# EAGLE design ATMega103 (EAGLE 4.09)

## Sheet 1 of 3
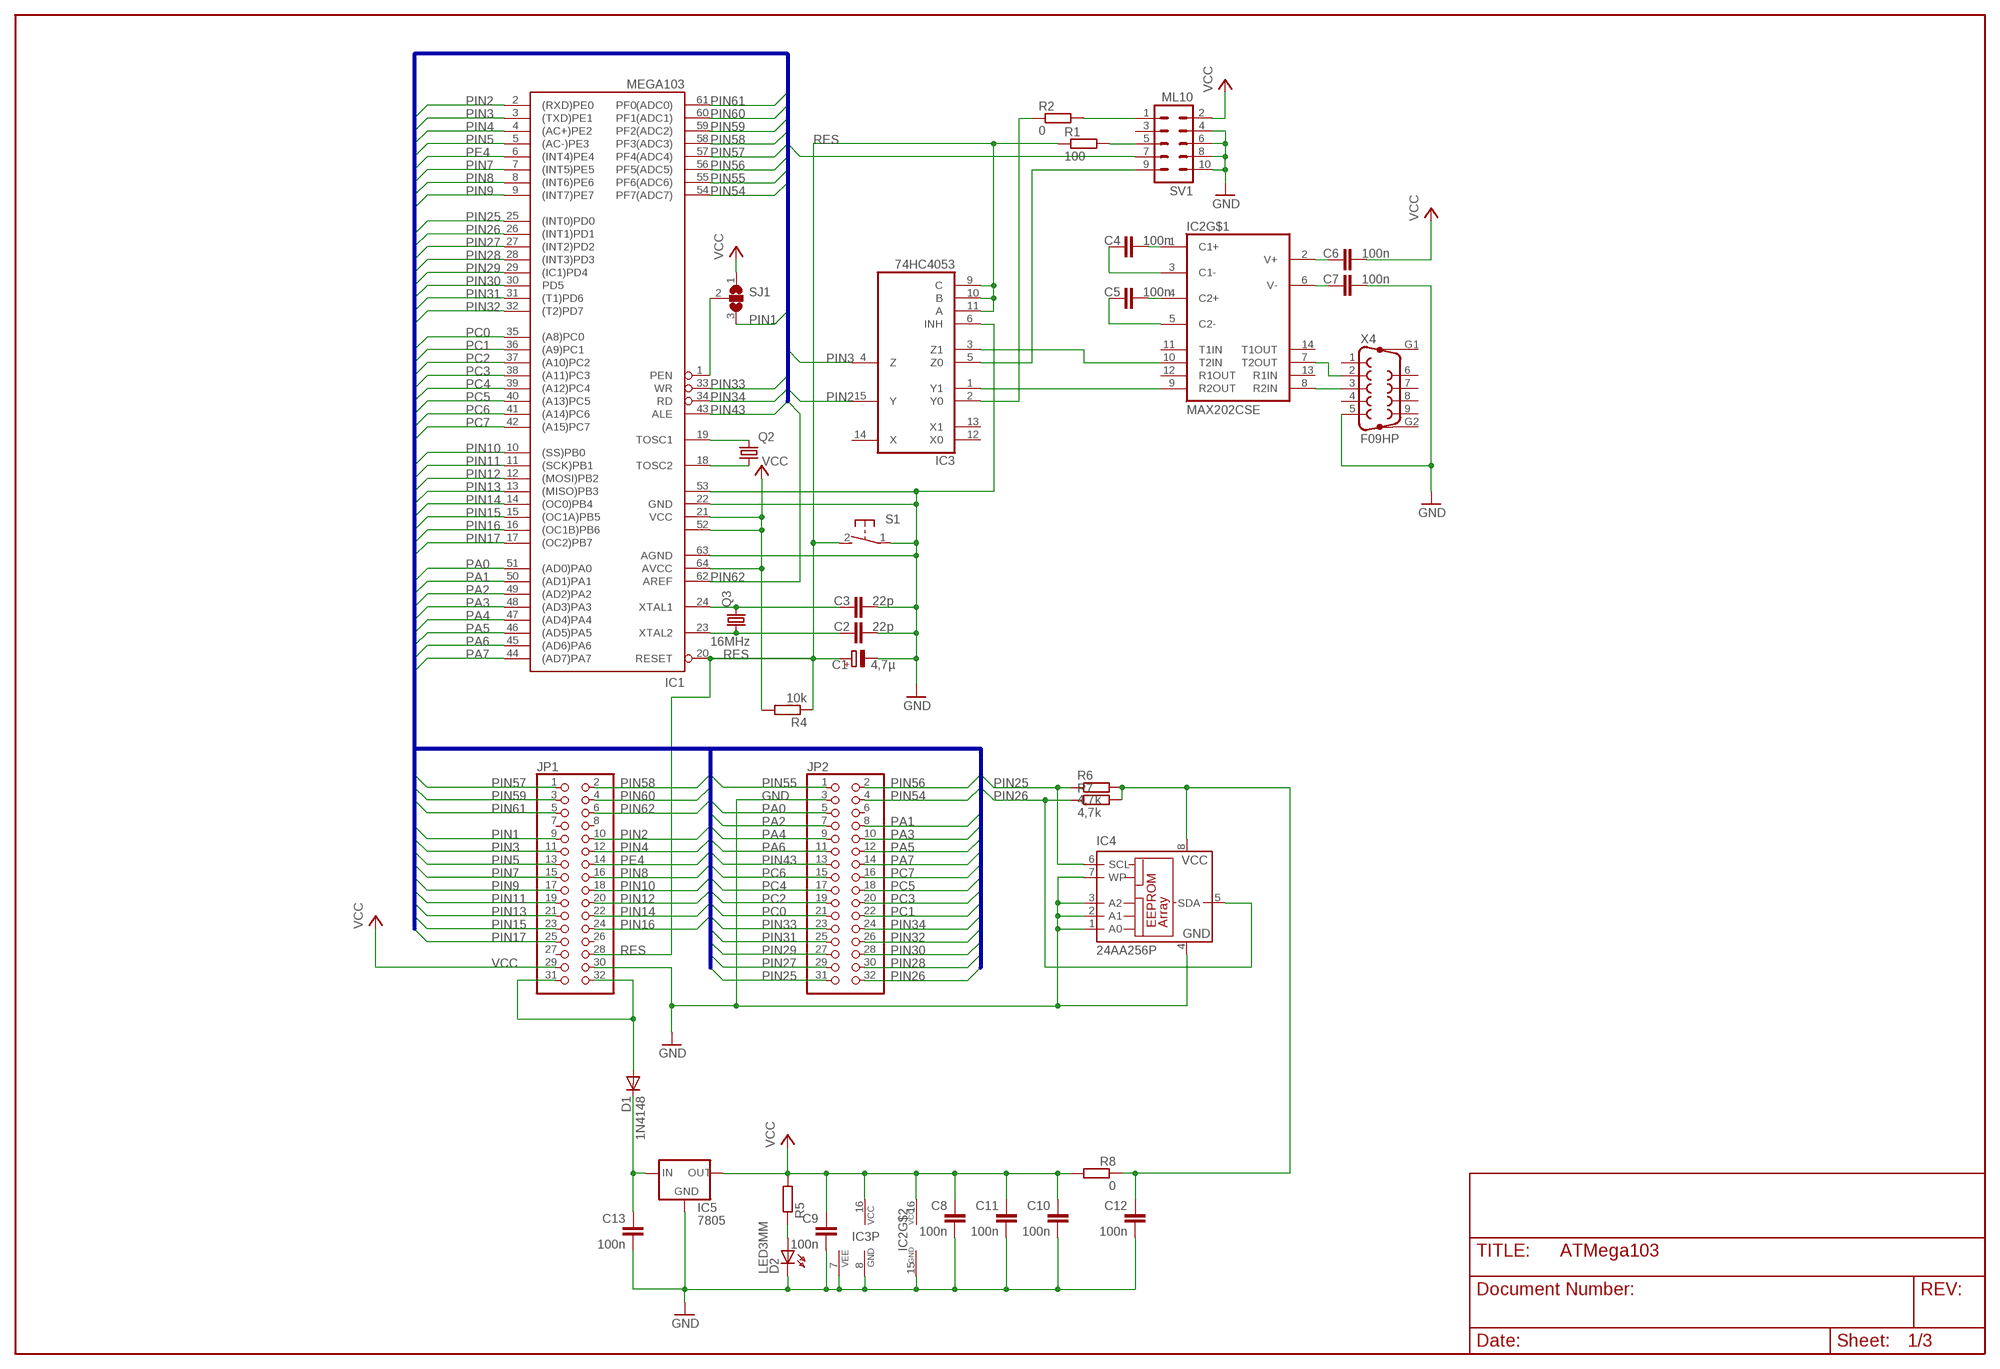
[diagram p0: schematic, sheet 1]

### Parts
C1  4,7µ  CPOL-EUE2-5  [E2-5]
C2  22p  C-EUC3216  [C3216]
C3  22p  C-EUC3216  [C3216]
C4  100n  C-EUC3216  [C3216]
C5  100n  C-EUC3216  [C3216]
C6  100n  C-EUC3216  [C3216]
C7  100n  C-EUC3216  [C3216]
C8  100n  C-EUC3216  [C3216]
C9  100n  C-EUC3216  [C3216]
C10  100n  C-EUC3216  [C3216]
C11  100n  C-EUC3216  [C3216]
C12  100n  C-EUC1206  [C1206]
C13  100n  C-EUC1206  [C1206]
D1  1N4148  DIODE-SOD106-R  [SOD106-R]
D2  LED3MM  [LED3MM]
IC1  MEGA103  [TQFP64]
IC2  MAX202CSE  [SO16]
IC3  74HC4053  4053D  [SO16]
IC4  24AA256P  [DIL8]
IC5  7805  78XXL  [78XXL]
JP1  PINHD-2X16  [2X16]
JP2  PINHD-2X16  [2X16]
Q2  TC26H  [TC26H]
Q3  16MHz  HC49/S  [HC49/S]
R1  100  R-EU_R3216  [R3216]
R2  0  R-EU_R3216  [R3216]
R4  10k  R-EU_R3216  [R3216]
R5  R-EU_R3216  [R3216]
R6  4,7k  R-EU_M3216  [M3216]
R7  4,7k  R-EU_M3216  [M3216]
R8  0  R-EU_R3216  [R3216]
S1  31-XX  [B3F-31XX]
SJ1  SJ2W  [SJ_2]
SV1  ML10  [ML10]
X4  F09HP  [F09HP]

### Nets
GND: C1.- C2.2 C3.2 C7.2 C8.2 C9.2 C10.2 C11.2 C12.2 C13.2 D2.K(C) IC1.22(GND) IC1.53(GND1) IC1.63(AGND) IC2.15(GND) IC3.6(INH) IC3.7(VEE) IC3.8(GND) IC4.1(A0) IC4.2(A1) IC4.3(A2) IC4.4(GND) IC4.7(WP) IC5.GND JP1.30 JP2.3 S1.1(P) SV1.4 SV1.6 SV1.8 SV1.10 X4.5 ; also sheet 2
N$1: C3.1 IC1.24(XTAL1) Q3.2
N$2: C2.1 IC1.23(XTAL2) Q3.1
N$3: IC1.19(TOSC1) Q2.1
N$4: IC1.18(TOSC2) Q2.2
N$9: D2.A R5.1
N$10: R2.2 SV1.1
N$11: D1.A JP1.31 JP1.32
N$12: IC1.1(PEN) SJ1.2
N$13: C12.1 IC4.8(VCC) R6.2 R7.2 R8.1
N$14: IC2.9(R2OUT) IC3.1(Y1)
N$16: IC3.5(Z0) SV1.9
N$17: IC3.2(Y0) R2.1
N$18: IC2.10(T2IN) IC3.3(Z1)
N$19: C4.2 IC2.1(C1+)
N$20: C5.2 IC2.4(C2+)
N$21: C5.1 IC2.5(C2-)
N$22: C6.1 IC2.2(V+)
N$23: C7.1 IC2.6(V-)
N$24: IC2.7(T2OUT) X4.2
N$25: IC2.8(R2IN) X4.3
N$26: C13.1 D1.C IC5.IN
N$28: R1.2 SV1.5
N$29: C4.1 IC2.3(C1-)
PA0: IC1.51((AD0)PA0) JP2.5 ; also sheet 2
PA1: IC1.50((AD1)PA1) JP2.8 ; also sheet 2
PA2: IC1.49((AD2)PA2) JP2.7 ; also sheet 2
PA3: IC1.48((AD3)PA3) JP2.10 ; also sheet 2
PA4: IC1.47((AD4)PA4) JP2.9 ; also sheet 2
PA5: IC1.46((AD5)PA5) JP2.12 ; also sheet 2
PA6: IC1.45((AD6)PA6) JP2.11 ; also sheet 2
PA7: IC1.44((AD7)PA7) JP2.14 ; also sheet 2
PC0: IC1.35((A8)PC0) JP2.21 ; also sheet 2
PC1: IC1.36((A9)PC1) JP2.22 ; also sheet 2
PC2: IC1.37((A10)PC2) JP2.19 ; also sheet 2
PC3: IC1.38((A11)PC3) JP2.20 ; also sheet 2
PC4: IC1.39((A12)PC4) JP2.17 ; also sheet 2
PC5: IC1.40((A13)PC5) JP2.18 ; also sheet 2
PC6: IC1.41((A14)PC6) JP2.15 ; also sheet 2
PC7: IC1.42((A15)PC7) JP2.16 ; also sheet 2
PE4: IC1.6((INT4)PE4) JP1.14 ; also sheet 2
PIN1: JP1.9 SJ1.3
PIN2: IC1.2((RXD)PE0) IC3.15(Y) JP1.10
PIN3: IC1.3((TXD)PE1) IC3.4(Z) JP1.11
PIN4: IC1.4((AC+)PE2) JP1.12
PIN5: IC1.5((AC-)PE3) JP1.13
PIN7: IC1.7((INT5)PE5) JP1.15
PIN8: IC1.8((INT6)PE6) JP1.16
PIN9: IC1.9((INT7)PE7) JP1.17
PIN10: IC1.10((SS)PB0) JP1.18
PIN11: IC1.11((SCK)PB1) JP1.19 SV1.7
PIN12: IC1.12((MOSI)PB2) JP1.20
PIN13: IC1.13((MISO)PB3) JP1.21
PIN14: IC1.14((OC0)PB4) JP1.22
PIN15: IC1.15((OC1A)PB5) JP1.23
PIN16: IC1.16((OC1B)PB6) JP1.24
PIN17: IC1.17((OC2)PB7) JP1.25
PIN25: IC1.25((INT0)PD0) IC4.6(SCL) JP2.31 R6.1
PIN26: IC1.26((INT1)PD1) IC4.5(SDA) JP2.32 R7.1
PIN27: IC1.27((INT2)PD2) JP2.29
PIN28: IC1.28((INT3)PD3) JP2.30
PIN29: IC1.29((IC1)PD4) JP2.27
PIN30: IC1.30(PD5) JP2.28
PIN31: IC1.31((T1)PD6) JP2.25
PIN32: IC1.32((T2)PD7) JP2.26
PIN33: IC1.33(WR) JP2.23
PIN34: IC1.34(RD) JP2.24
PIN43: IC1.43(ALE) JP2.13
PIN54: IC1.54(PF7(ADC7)) JP2.4
PIN55: IC1.55(PF6(ADC6)) JP2.1
PIN56: IC1.56(PF5(ADC5)) JP2.2
PIN57: IC1.57(PF4(ADC4)) JP1.1
PIN58: IC1.58(PF3(ADC3)) JP1.2
PIN59: IC1.59(PF2(ADC2)) JP1.3
PIN60: IC1.60(PF1(ADC1)) JP1.4
PIN61: IC1.61(PF0(ADC0)) JP1.5
PIN62: IC1.62(AREF) JP1.6
RES: C1.+ IC1.20(RESET) IC3.9(C) IC3.10(B) IC3.11(A) JP1.28 R1.1 R4.1 S1.2(S)
VCC: C6.2 C8.1 C9.1 C10.1 C11.1 IC1.21(VCC) IC1.52(VCC1) IC1.64(AVCC) IC2.16(VCC) IC3.16(VCC) IC5.OUT JP1.29 R4.2 R5.2 R8.2 SJ1.1 SV1.2 ; also sheet 2
Unconnected: IC2.11(T1IN) IC2.12(R1OUT) IC2.13(R1IN) IC2.14(T1OUT) IC3.12(X0) IC3.13(X1) IC3.14(X) JP1.7 JP1.8 JP1.26 JP1.27 JP2.6 SV1.3 X4.1 X4.4 X4.6 X4.7 X4.8 X4.9 X4.G1 X4.G2

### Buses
PIN[1..64]

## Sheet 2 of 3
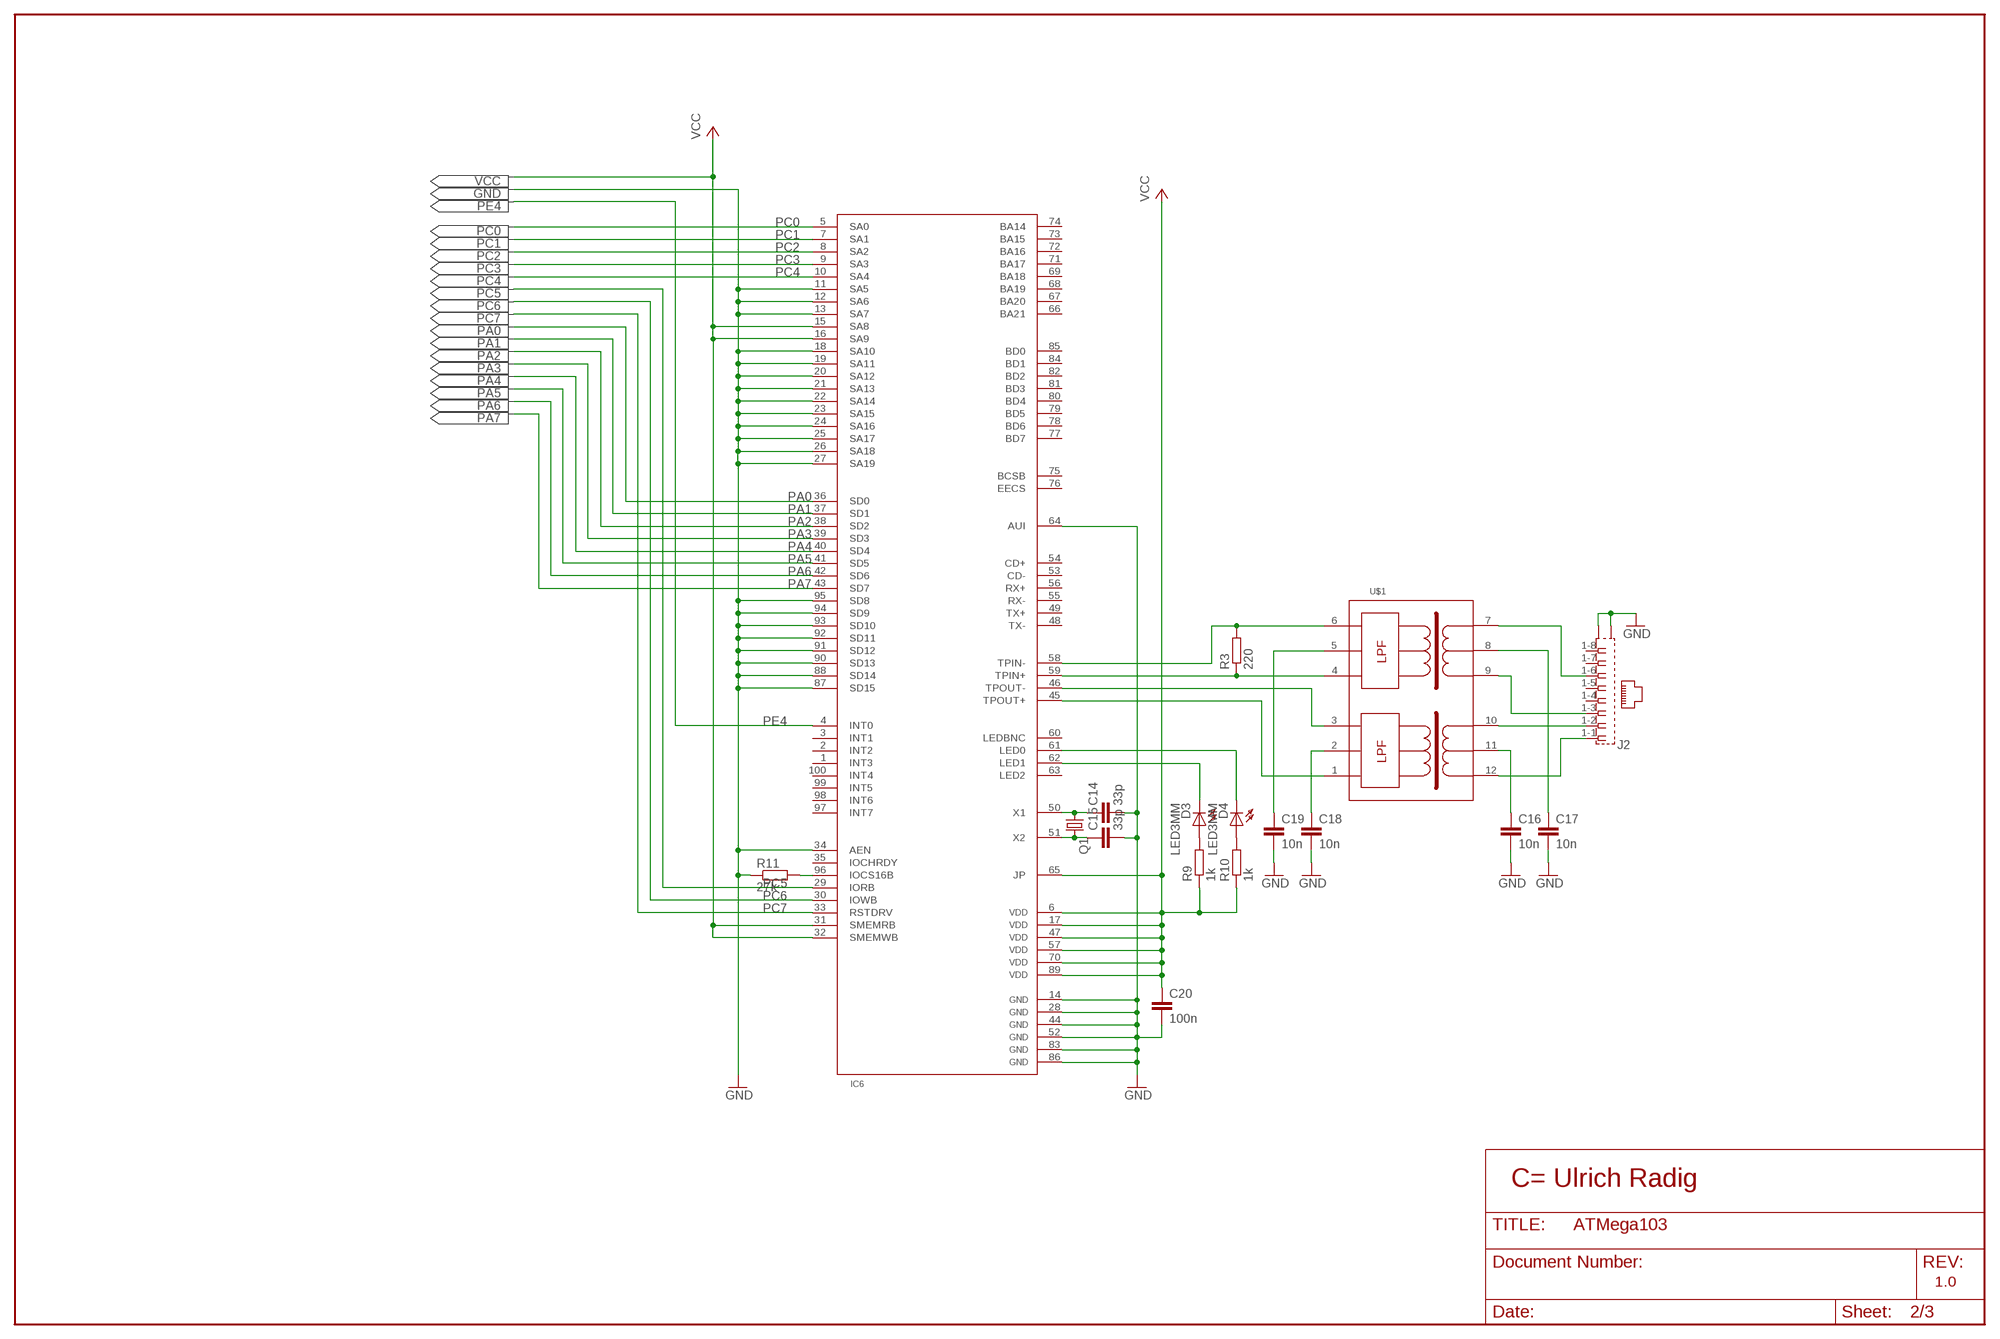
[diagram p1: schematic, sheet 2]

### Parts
C14  33p  C-EUC0805  [C0805]
C15  33p  C-EUC0805  [C0805]
C16  10n  C-EUC1206  [C1206]
C17  10n  C-EUC1206  [C1206]
C18  10n  C-EUC1206  [C1206]
C19  10n  C-EUC1206  [C1206]
C20  100n  C-EUC1206  [C1206]
D3  LED3MM  [LED3MM]
D4  LED3MM  [LED3MM]
IC6  RTL8019  [TQPF100]
J2  557786-1  [557786-1]
Q1  HC49U-H  [HC49U-H]
R3  220  R-EU_R1206  [R1206]
R9  1k  R-EU_M0805  [M0805]
R10  1k  R-EU_M0805  [M0805]
R11  27k  R-EU_M1206  [M1206]
U$1  20F001  [DIL16/12]

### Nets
GND: C14.2 C15.2 C16.2 C17.2 C18.2 C19.2 C20.2 IC6.11(SA5) IC6.12(SA6) IC6.13(SA7) IC6.14(G1) IC6.18(SA10) IC6.19(SA11) IC6.20(SA12) IC6.21(SA13) IC6.22(SA14) IC6.23(SA15) IC6.24(SA16) IC6.25(SA17) IC6.26(SA18) IC6.27(SA19) IC6.28(G2) IC6.34(AEN) IC6.44(G3) IC6.52(G4) IC6.64(AUI) IC6.83(G5) IC6.86(G6) IC6.87(SD15) IC6.88(SD14) IC6.90(SD13) IC6.91(SD12) IC6.92(SD11) IC6.93(SD10) IC6.94(SD9) IC6.95(SD8) J2.G1(S2) J2.G2(S1) R11.1 ; also sheet 1
N$15: J2.1-1 U$1.12
N$27: J2.1-2 U$1.10
N$30: J2.1-3 U$1.9
N$31: J2.1-6 U$1.7
N$32: IC6.58(TPIN-) R3.2 U$1.6
N$33: IC6.59(TPIN+) R3.1 U$1.4
N$34: IC6.46(TPOUT-) U$1.3
N$35: IC6.45(TPOUT+) U$1.1
N$36: C18.1 U$1.2
N$37: C19.1 U$1.5
N$38: C16.1 U$1.11
N$39: C17.1 U$1.8
N$40: C15.1 IC6.51(X2) Q1.2
N$41: C14.1 IC6.50(X1) Q1.1
N$42: D4.K(C) IC6.61(LED0)
N$43: D3.K(C) IC6.62(LED1)
N$44: D3.A R9.2
N$45: D4.A R10.2
N$46: IC6.96(IOCS16B) R11.2
PA0: IC6.36(SD0) ; also sheet 1
PA1: IC6.37(SD1) ; also sheet 1
PA2: IC6.38(SD2) ; also sheet 1
PA3: IC6.39(SD3) ; also sheet 1
PA4: IC6.40(SD4) ; also sheet 1
PA5: IC6.41(SD5) ; also sheet 1
PA6: IC6.42(SD6) ; also sheet 1
PA7: IC6.43(SD7) ; also sheet 1
PC0: IC6.5(SA0) ; also sheet 1
PC1: IC6.7(SA1) ; also sheet 1
PC2: IC6.8(SA2) ; also sheet 1
PC3: IC6.9(SA3) ; also sheet 1
PC4: IC6.10(SA4) ; also sheet 1
PC5: IC6.29(IORB) ; also sheet 1
PC6: IC6.30(IOWB) ; also sheet 1
PC7: IC6.33(RSTDRV) ; also sheet 1
PE4: IC6.4(INT0) ; also sheet 1
VCC: C20.1 IC6.6(V1) IC6.15(SA8) IC6.16(SA9) IC6.17(V2) IC6.31(SMEMRB) IC6.32(SMEMWB) IC6.47(V3) IC6.57(V4) IC6.65(JP) IC6.70(V5) IC6.89(V6) R9.1 R10.1 ; also sheet 1
Unconnected: IC6.1(INT3) IC6.2(INT2) IC6.3(INT1) IC6.35(IOCHRDY) IC6.48(TX-) IC6.49(TX+) IC6.53(CD-) IC6.54(CD+) IC6.55(RX-) IC6.56(RX+) IC6.60(LEDBNC) IC6.63(LED2) IC6.66(BA21) IC6.67(BA20) IC6.68(BA19) IC6.69(BA18) IC6.71(BA17) IC6.72(BA16) IC6.73(BA15) IC6.74(BA14) IC6.75(BCSB) IC6.76(EECS) IC6.77(BD7) IC6.78(BD6) IC6.79(BD5) IC6.80(BD4) IC6.81(BD3) IC6.82(BD2) IC6.84(BD1) IC6.85(BD0) IC6.97(INT7) IC6.98(INT6) IC6.99(INT5) IC6.100(INT4) J2.1-4 J2.1-5 J2.1-7 J2.1-8

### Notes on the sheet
- C= Ulrich Radig
- 1.0

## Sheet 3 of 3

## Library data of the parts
C1 = rcl:CPOL-EU: POLARIZED CAPACITOR, European symbol
C2-C20 = rcl:C-EU: CAPACITOR, European symbol
D1 = diode:DIODE-: DIODE
D2-D4 = led:LED3MM: LED
IC1 = atmel:MEGA103*: MICROCONTROLLER Low-voltage (L) 128 Kbytes FLASH 4 Kbytes SRAM 2 Kbytes EEPROM UART RTC 8-channel 10 bit ADC
IC2 = maxim:MAX202CSE
IC3 = 40xx:4053: Triple 2-channel ANALOG MULTIPLEXER
IC4 = microchip:24*: Serial EEPROM I2C
IC5 = v-reg:78XXL: VOLTAGE REGULATOR
IC6 = Realtek:RTL8019
J2 = con-amp:557786-1: AMP CONNECTOR
JP1 JP2 = pinhead:PINHD-2X16: PIN HEADER
Q1 = crystal:HC49U-H: CRYSTAL
Q2 = crystal:TC26H: CRYSTAL
Q3 = crystal:HC49/S: CRYSTAL
R1-R11 = rcl:R-EU_: RESISTOR, European symbol
S1 = switch-omron:31-XX: OMRON SWITCH
SJ1 = jumper:SJ2W: SMD solder JUMPER
SV1 = CON-ML:ML10
U$1 = Realtek:20F001
X4 = SUBD-A:F09HP

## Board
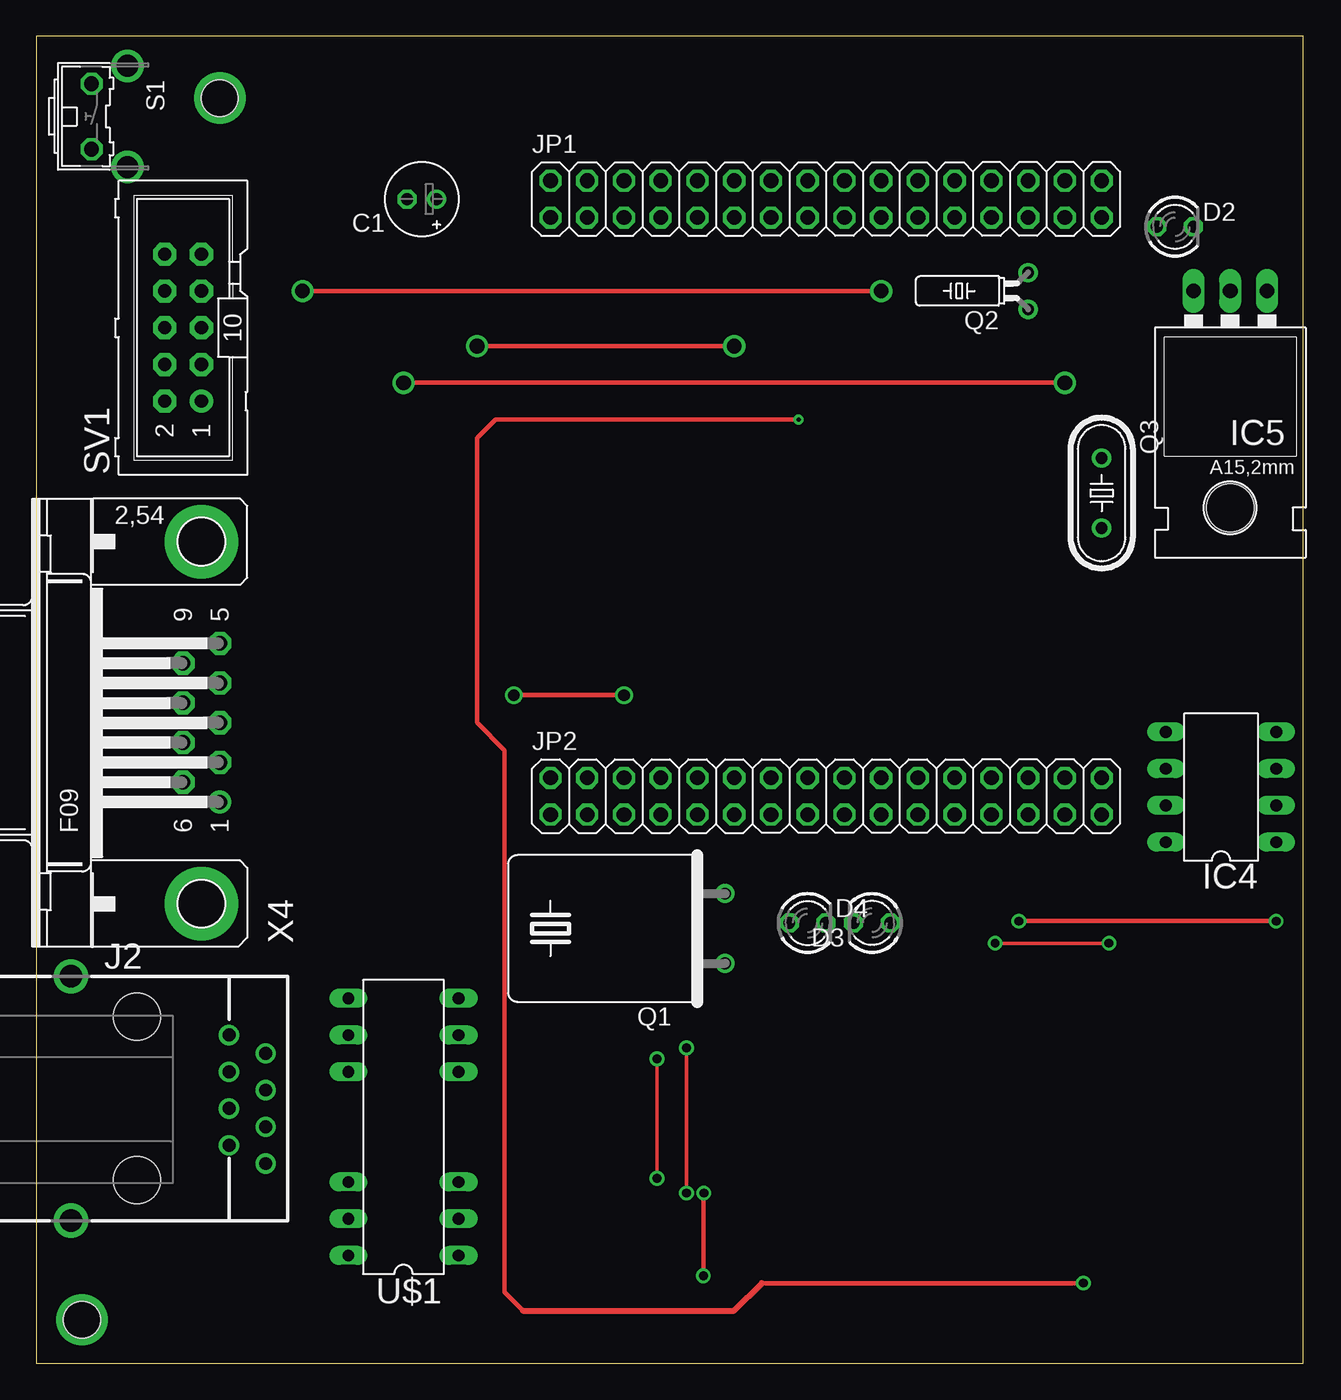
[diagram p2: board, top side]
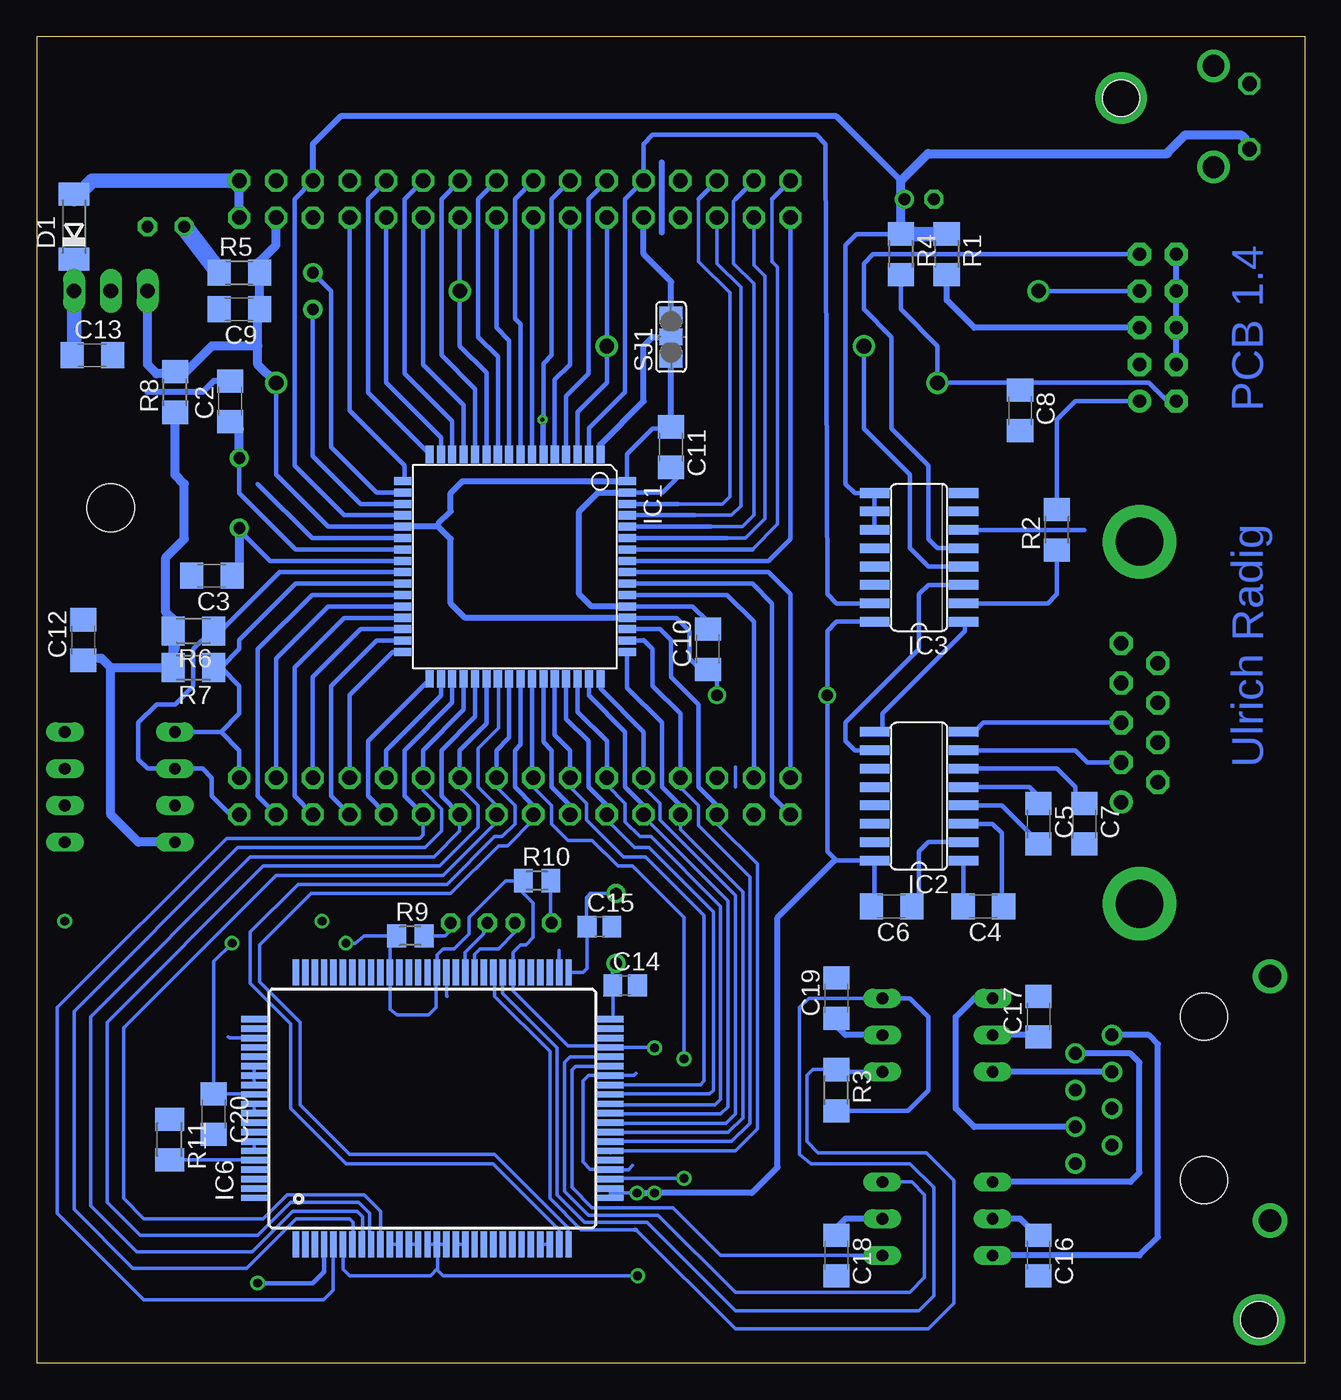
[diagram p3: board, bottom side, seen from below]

Size 87.61 x 91.74 mm. Coordinates in mm from the lower left corner, seen from the top.
Outline: 0,0 87.61,0 87.61,91.74 0,91.74 0,0
Copper layers (1*16): Top 0.035mm / dielectric 1.5mm / Bottom 0.035mm
Design rules "default": minimum track width 10mil, minimum drill 24mil, track to track 16mil, track to pad 16mil, pad to pad 16mil, via to via 16mil, smd to smd 16mil, copper to edge 40mil, drill to drill 8mil, minimum pad ring 10mil, minimum via ring 8mil, stop-mask expansion 4mil, vias tented up to drill 0mil, thermal gap 10mil
Holes 2.54 mm at 12.69,87.46 3.17,3.01

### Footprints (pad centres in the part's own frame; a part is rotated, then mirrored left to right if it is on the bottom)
E2-5 = drill 0.813 pad 1.27 round: + -1.016,0 | drill 0.813 pad 1.27 octagon: - 1.016,0
C3216 = smd 1.6 x 1.8: 1 -1.4,0; 2 1.4,0
C1206 = smd 1.6 x 1.8: 1 -1.4,0; 2 1.4,0
C0805 = smd 1.3 x 1.5: 1 -0.85,0; 2 0.85,0
SOD106-R = smd 1.6 x 2.1: A 2.25,0; C -2.25,0
LED3MM = drill 0.813 octagon: A -1.27,0; K 1.27,0
TQFP64 = smd 1.194 x 0.559: 1 -7.76,5.905; 2 -7.76,5.118; 3 -7.76,4.331; 4 -7.76,3.543; 5 -7.76,2.756; 6 -7.76,1.968; 7 -7.76,1.181; 8 -7.76,0.394; 9 -7.76,-0.394; 10 -7.76,-1.181; 11 -7.76,-1.968; 12 -7.76,-2.756; 13 -7.76,-3.543; 14 -7.76,-4.331; 15 -7.76,-5.118; 16 -7.76,-5.905; 33 7.76,-5.905; 34 7.76,-5.118; 35 7.76,-4.331; 36 7.76,-3.543; 37 7.76,-2.756; 38 7.76,-1.968; 39 7.76,-1.181; 40 7.76,-0.394; 41 7.76,0.394; 42 7.76,1.181; 43 7.76,1.968; 44 7.76,2.756; 45 7.76,3.543; 46 7.76,4.331; 47 7.76,5.118; 48 7.76,5.905 | smd 0.559 x 1.194: 17 -5.905,-7.76; 18 -5.118,-7.76; 19 -4.331,-7.76; 20 -3.543,-7.76; 21 -2.756,-7.76; 22 -1.968,-7.76; 23 -1.181,-7.76; 24 -0.394,-7.76; 25 0.394,-7.76; 26 1.181,-7.76; 27 1.968,-7.76; 28 2.756,-7.76; 29 3.543,-7.76; 30 4.331,-7.76; 31 5.118,-7.76; 32 5.905,-7.76; 49 5.905,7.76; 50 5.118,7.76; 51 4.331,7.76; 52 3.543,7.76; 53 2.756,7.76; 54 1.968,7.76; 55 1.181,7.76; 56 0.394,7.76; 57 -0.394,7.76; 58 -1.181,7.76; 59 -1.968,7.76; 60 -2.756,7.76; 61 -3.543,7.76; 62 -4.331,7.76; 63 -5.118,7.76; 64 -5.905,7.76
SO16 = smd 0.66 x 2.032: 1 -4.445,-3.073; 2 -3.175,-3.073; 3 -1.905,-3.073; 4 -0.635,-3.073; 5 0.635,-3.073; 6 1.905,-3.073; 7 3.175,-3.073; 8 4.445,-3.073; 9 4.445,3.073; 10 3.175,3.073; 11 1.905,3.073; 12 0.635,3.073; 13 -0.635,3.073; 14 -1.905,3.073; 15 -3.175,3.073; 16 -4.445,3.073
DIL8 = drill 0.813 long: 1 -3.81,-3.81; 2 -1.27,-3.81; 3 1.27,-3.81; 4 3.81,-3.81; 5 3.81,3.81; 6 1.27,3.81; 7 -1.27,3.81; 8 -3.81,3.81
78XXL = drill 1.016 long: GND 0,-3.81; IN -2.54,-3.81; OUT 2.54,-3.81 | hole 3.302: 0,11.176
TQPF100 = smd 1.8 x 0.44: 1 -9.395,9.425; 2 -9.395,8.775; 3 -9.395,8.125; 4 -9.395,7.475; 5 -9.395,6.825; 6 -9.395,6.175; 7 -9.395,5.525; 8 -9.395,4.875; 9 -9.395,4.225; 10 -9.395,3.575; 11 -9.395,2.925; 12 -9.395,2.275; 13 -9.395,1.625; 14 -9.395,0.975; 15 -9.395,0.325; 16 -9.395,-0.325; 17 -9.395,-0.975; 18 -9.395,-1.625; 19 -9.395,-2.275; 20 -9.395,-2.925; 21 -9.395,-3.575; 22 -9.395,-4.225; 23 -9.395,-4.875; 24 -9.395,-5.525; 25 -9.395,-6.175; 26 -9.395,-6.825; 27 -9.395,-7.475; 28 -9.395,-8.125; 29 -9.395,-8.775; 30 -9.395,-9.425; 51 9.395,-9.425; 52 9.395,-8.775; 53 9.395,-8.125; 54 9.395,-7.475; 55 9.395,-6.825; 56 9.395,-6.175; 57 9.395,-5.525; 58 9.395,-4.875; 59 9.395,-4.225; 60 9.395,-3.575; 61 9.395,-2.925; 62 9.395,-2.275; 63 9.395,-1.625; 64 9.395,-0.975; 65 9.395,-0.325; 66 9.395,0.325; 67 9.395,0.975; 68 9.395,1.625; 69 9.395,2.275; 70 9.395,2.925; 71 9.395,3.575; 72 9.395,4.225; 73 9.395,4.875; 74 9.395,5.525; 75 9.395,6.175; 76 9.395,6.825; 77 9.395,7.475; 78 9.395,8.125; 79 9.395,8.775; 80 9.395,9.425 | smd 0.44 x 1.8: 31 -6.175,-12.32; 32 -5.525,-12.32; 33 -4.875,-12.32; 34 -4.225,-12.32; 35 -3.575,-12.32; 36 -2.925,-12.32; 37 -2.275,-12.32; 38 -1.625,-12.32; 39 -0.975,-12.32; 40 -0.325,-12.32; 41 0.325,-12.32; 42 0.975,-12.32; 43 1.625,-12.32; 44 2.275,-12.32; 45 2.925,-12.32; 46 3.575,-12.32; 47 4.225,-12.32; 48 4.875,-12.32; 49 5.525,-12.32; 50 6.175,-12.32; 81 6.175,12.32; 82 5.525,12.32; 83 4.875,12.32; 84 4.225,12.32; 85 3.575,12.32; 86 2.925,12.32; 87 2.275,12.32; 88 1.625,12.32; 89 0.975,12.32; 90 0.325,12.32; 91 -0.325,12.32; 92 -0.975,12.32; 93 -1.625,12.32; 94 -2.275,12.32; 95 -2.925,12.32; 96 -3.575,12.32; 97 -4.225,12.32; 98 -4.875,12.32; 99 -5.525,12.32; 100 -6.175,12.32
557786-1 = drill 0.889 round: 1-1 -4.445,6.35; 1-2 -3.175,8.89; 1-3 -1.905,6.35; 1-4 -0.635,8.89; 1-5 0.635,6.35; 1-6 1.905,8.89; 1-7 3.175,6.35; 1-8 4.445,8.89 | drill 1.575 pad 2.184 round: G1 -8.509,-4.572; G2 8.382,-4.572 | hole 3.251: -5.715,0; 5.588,0
2X16 = drill 1.016 octagon: 1 -19.05,-1.27; 2 -19.05,1.27; 3 -16.51,-1.27; 4 -16.51,1.27; 5 -13.97,-1.27; 6 -13.97,1.27; 7 -11.43,-1.27; 8 -11.43,1.27; 9 -8.89,-1.27; 10 -8.89,1.27; 11 -6.35,-1.27; 12 -6.35,1.27; 13 -3.81,-1.27; 14 -3.81,1.27; 15 -1.27,-1.27; 16 -1.27,1.27; 17 1.27,-1.27; 18 1.27,1.27; 19 3.81,-1.27; 20 3.81,1.27; 21 6.35,-1.27; 22 6.35,1.27; 23 8.89,-1.27; 24 8.89,1.27; 25 11.43,-1.27; 26 11.43,1.27; 27 13.97,-1.27; 28 13.97,1.27; 29 16.51,-1.27; 30 16.51,1.27; 31 19.05,-1.27; 32 19.05,1.27
HC49U-H = drill 0.813 round: 1 -2.413,-5.08; 2 2.413,-5.08
TC26H = drill 0.813 round: 1 -1.27,0; 2 1.27,0
HC49/S = drill 0.813 round: 1 -2.413,0; 2 2.413,0
R3216 = smd 1.6 x 1.8: 1 -1.4,0; 2 1.4,0
R1206 = smd 1.6 x 1.803: 1 -1.422,0; 2 1.422,0
M3216 = smd 1.6 x 2: 1 -1.4,0; 2 1.4,0
M0805 = smd 1.3 x 1.6: 1 -0.95,0; 2 0.95,0
M1206 = smd 1.6 x 2: 1 -1.4,0; 2 1.4,0
B3F-31XX = drill 1.016 octagon: 1 -2.261,-1.245; 2 2.261,-1.245 | drill 1.499 pad 2.159 round: 3 -3.505,1.245; 4 3.505,1.245
SJ_2 = smd 1.168 x 1.6: 1 -1.524,0; 2 0,0; 3 1.524,0
ML10 = drill 0.914 pad 1.6 round: 1 -5.08,-1.27 | drill 0.914 pad 1.6 octagon: 2 -5.08,1.27; 3 -2.54,-1.27; 4 -2.54,1.27; 5 0,-1.27; 6 0,1.27; 7 2.54,-1.27; 8 2.54,1.27; 9 5.08,-1.27; 10 5.08,1.27
DIL16/12 = drill 0.813 long: 1 -8.89,-3.81; 2 -6.35,-3.81; 3 -3.81,-3.81; 4 3.81,-3.81; 5 6.35,-3.81; 6 8.89,-3.81; 7 8.89,3.81; 8 6.35,3.81; 9 3.81,3.81; 10 -3.81,3.81; 11 -6.35,3.81; 12 -8.89,3.81
F09HP = drill 1.016 pad 1.6 round: 1 -5.486,-1.27 | drill 1.016 pad 1.6 octagon: 2 -2.743,-1.27; 3 0,-1.27; 4 2.743,-1.27; 5 5.486,-1.27; 6 -4.115,1.27; 7 -1.372,1.27; 8 1.372,1.27; 9 4.115,1.27 | drill 3.302 pad 5.08 round: G1 -12.522,0; G2 12.522,0

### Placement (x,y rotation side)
C1  26.67,80.48 180 top
C2  74.29,66.51 90 bottom
C3  75.56,54.45 180 bottom
C4  22.22,31.59 180 bottom
C5  18.41,37.3 270 bottom
C6  28.57,31.59 180 bottom
C7  15.23,37.3 270 bottom
C8  19.68,65.88 270 bottom
C9  73.66,72.86 180 bottom
C10  41.27,49.37 90 bottom
C11  43.81,63.34 270 bottom
C12  84.45,50 90 bottom
C13  83.81,69.68 0 bottom
C14  46.98,26.12 0 bottom
C15  48.76,30.19 0 bottom
C16  18.41,7.46 270 bottom
C17  18.41,23.96 90 bottom
C18  32.38,7.46 270 bottom
C19  32.38,25.23 90 bottom
C20  75.43,17.23 270 bottom
D1  85.09,78.57 90 bottom
D2  78.73,78.57 0 top
D3  57.78,30.44 180 top
D4  53.34,30.44 0 top
IC1  54.6,55.08 270 bottom
IC2  26.67,39.2 90 bottom
IC3  26.67,55.72 90 bottom
IC4  81.91,39.84 90 top
IC5  82.55,70.32 180 top
IC6  60.32,17.62 90 bottom
J2  6.98,18.25 270 top
JP1  54.6,80.48 0 top
JP2  54.6,39.2 0 top
Q1  42.54,30.06 90 top
Q2  68.58,74.13 90 top
Q3  73.66,60.16 270 top
R1  24.76,76.67 270 bottom
R2  17.14,57.62 90 bottom
R3  32.38,18.89 270 bottom
R4  27.94,76.67 270 bottom
R5  73.66,75.4 0 bottom
R6  76.83,50.63 180 bottom
R7  76.83,48.09 180 bottom
R8  78.1,67.14 90 bottom
R9  61.84,29.55 0 bottom
R10  53.08,33.36 0 bottom
R11  78.48,15.46 270 bottom
S1  5.08,86.19 270 top
SJ1  43.81,70.95 90 bottom
SV1  10.15,71.59 90 top
U$1  25.39,16.35 90 top
X4  11.42,44.29 90 top

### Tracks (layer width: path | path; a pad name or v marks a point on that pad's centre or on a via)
GND  (via drill 0.61 pad 1.02)
  Top 0.305: v67.94,30.57 v85.72,30.57
  Bottom 0.254: IC6.27 52.83,8.22 52.82,8.22 IC6.28 | IC6.34 46.77,13.39 46.48,13.68 | IC6.19 58.16,8.22 IC6.18 | IC6.13 61.85,8.22 61.84,8.22 IC6.14 | 63.36,8.22 IC6.11 | IC6.12 63.36,8.22 | 63.36,8.22 63.37,8.22 | IC6.44 46.36,19.89 46.22,20.03 | 39.36,39.84 39.36,41.24 | IC6.52 51.56,27.02 51.56,28.54 | 48.76,19.9 49.52,19.9 49.91,19.52 49.91,13.93 49.4,13.42 48,13.42 | IC6.83 74.34,22.49 74.42,22.57 | IC6.86 72.64,19.9 IC6.87 72.64,19.27 IC6.88 | IC6.90 72.64,17.87 IC6.91 | IC6.94 72.64,15.33 IC6.95 | IC6.64 59.34,25.4 59.3,25.36
  Bottom 0.305: IC1.22 68.64,57.05 72.39,60.8 | IC1.63 44.41,60.2 43.17,61.43 | 15.23,57.62 IC3.6 | IC1.53 42.32,52.32 41.27,51.27 | IC6.44 48.12,19.89 48.13,19.9 48.76,19.9 | IC6.34 48,13.42
  Bottom 0.406: SV1.10 SV1.8 SV1.6 SV1.4 | IC1.63 48.85,60.2 50.16,58.89 50.16,53.18 49.31,52.32 IC1.53 | C2.2 75.43,67.91 76.2,67.14 80.01,67.14 | C10.2 41.27,51.27 | 44.45,78.19 44.45,83.02
N$1
  Bottom 0.305: IC1.24 71.51,55.47 73.66,57.62
  Bottom 0.406: 74.16,54.58 C3.1 | 73.66,57.62 Q3.2
  Bottom 0.61: 73.66,57.62 73.66,54.45 73.79,54.58 74.16,54.58
N$2
  Bottom 0.305: IC1.23 69.76,56.26 73.66,60.16 Q3.1 73.66,62.7 | C2.1 74.29,65.24 73.66,64.6
  Bottom 0.61: Q3.1 73.66,64.6
N$3
  Bottom 0.305: IC1.19 65.29,59.41 68.58,62.7 Q2.1
N$4
  Bottom 0.305: IC1.18 64.17,60.2 67.31,63.34 67.31,74.13 Q2.2
N$5  (via drill 2.54)
  other vias: 12.69,87.46
N$8  (via drill 2.54)
  other vias: 3.17,3.01
N$9
  Bottom 1.27: R5.1 D2.A
N$10
  Bottom 0.305: SV1.1 15.87,66.51 17.14,65.24 R2.2 17.14,58.89
N$11
  Bottom 0.61: JP1.31 JP1.32 | 85.09,80.48 D1.A
  Bottom 1.016: JP1.32 83.81,81.75 85.09,80.48
N$12
  Bottom 0.406: SJ1.2 45.08,70.95 45.71,70.32 45.71,66.51 48.7,63.53 IC1.1
N$13
  Bottom 0.406: 84.45,48.73 C12.1
  Bottom 0.61: R8.1 78.1,61.43 77.47,60.8 77.47,56.98 78.73,55.72 78.73,51.91 78.1,51.27 78.1,49.37 R6.2 78.23,48.23 | 78.1,48.09 R7.2 78.23,48.23 | 78.1,48.09 78.23,48.23 | IC4.8 80.64,36.03 82.55,37.94 82.55,48.09 | 82.55,48.09 78.1,48.09 | 84.45,48.73 83.18,48.73 82.55,48.09
N$14
  Bottom 0.305: IC3.1 23.49,51.27 23.49,50.63 29.21,44.92 29.21,43.65 IC2.9 29.84,43.65
N$15
  Bottom 0.406: J2.1-1 10.79,22.7 10.15,22.06 10.15,8.73 11.42,7.46 U$1.12
N$16
  Bottom 0.305: SV1.9 29.84,76.67 30.48,76.03 30.48,72.86 28.57,70.95 28.57,64.6 26.03,62.06 26.03,56.98 25.39,56.35 IC3.5 23.49,56.35
N$17
  Bottom 0.305: IC3.2 17.78,52.54 17.14,53.18 R2.1
N$18
  Bottom 0.305: IC3.3 26.03,53.81 26.67,53.18 26.67,49.37 31.75,44.29 31.75,43.02 31.11,42.38 IC2.10
N$19
  Bottom 0.305: C4.2 23.49,31.59 23.59,31.69 IC2.1
N$20
  Bottom 0.305: IC2.4 20.95,38.57 18.41,36.03 C5.2
N$21
  Bottom 0.305: C5.1 18.41,39.2 19.05,39.84 IC2.5
N$22
  Bottom 0.305: IC2.2 26.03,36.03 26.67,35.4 26.67,32.22 27.3,31.59 C6.1
N$23
  Bottom 0.305: C7.1 15.87,38.7 | 15.87,38.7 15.87,38.57 | 15.87,38.7 15.87,39.84 17.14,41.11 IC2.6
N$24
  Bottom 0.305: X4.2 15.03,41.54 15.87,42.38 IC2.7
N$25
  Bottom 0.305: IC2.8 22.86,43.65 22.22,44.29 X4.3
N$26
  Bottom 0.61: C13.1 85.09,69.68
  Bottom 1.016: 85.09,69.68 IC5.IN D1.C
N$27
  Bottom 0.406: J2.1-2 12.06,21.43 11.42,20.79 11.42,13.17 12.06,12.54 U$1.10
N$28
  Bottom 0.406: SV1.5 22.86,71.59 24.76,73.49 R1.2
N$29
  Bottom 0.305: IC2.3 21.59,37.3 20.95,36.66 20.95,31.59 C4.1
N$30
  Bottom 0.406: J2.1-3 U$1.9
N$31
  Bottom 0.406: J2.1-6 22.86,16.35 24.12,17.62 24.12,23.96 22.86,25.23 U$1.7
N$32
  Bottom 0.254: IC6.58 55.45,25.57 51.68,21.81 51.68,11.65 49.78,9.74 45.46,9.74 39.36,3.65 26.67,3.65 25.65,4.66 25.65,12.15 27.3,13.81 34.16,13.81 34.92,14.44 34.92,24.6 34.28,25.23 29.46,25.23 29.33,25.36 U$1.6
  Bottom 0.305: R3.2 27.45,17.46 26.03,18.89 26.03,23.96 27.3,25.23 U$1.6
N$33
  Bottom 0.254: R3.1 34.01,20.31 34.41,19.9 34.41,15.33 33.65,14.57 26.16,14.57 24.25,12.66 24.25,4.15 26.03,2.38 39.36,2.38 46.22,9.23 | 46.35,9.23 50.03,9.23 52.19,11.39 52.19,21.55 56,25.36 56,26.89 56.13,27.01 | 56.13,27.01 | 56.13,27.01 IC6.59
  Bottom 0.305: R3.1 32.38,20.16 U$1.4 | 46.22,9.23 46.35,9.23
N$34
  Bottom 0.254: U$1.3 27.17,12.54 26.28,11.65 26.28,5.93 27.3,4.92 39.36,4.92 44.7,10.25 49.52,10.25 51.18,11.9 51.18,20.79 50.79,21.17 48.13,21.17 48,21.3 IC6.46
N$35
  Bottom 0.254: U$1.1 40.38,7.46 43.68,10.76 49.27,10.76 50.67,12.15 50.67,20.28 50.41,20.54 IC6.45
N$36
  Bottom 0.406: U$1.2 31.75,10 32.38,9.36 C18.1 32.38,8.73
N$37
  Bottom 0.406: C19.1 32.38,23.33 31.75,22.7 U$1.5
N$38
  Bottom 0.406: C16.1 18.54,8.86 19.68,10 U$1.11
N$39
  Bottom 0.406: C17.1 18.41,22.7 U$1.8
N$40
  Bottom 0.254: Q1.2 49.4,32.47 49.65,32.22 49.65,30.32 49.52,30.19 C15.1 49.61,27.31 49.91,27.01 50.79,27.01 IC6.51
N$41
  Bottom 0.254: Q1.1 47.87,27.78 47.87,26.38 47.75,26.25 47.84,26.16 C14.1 47.84,24 48,23.84 IC6.50
N$42
  Bottom 0.254: D4.K 54.6,29.81 55.75,28.66 57.02,28.66 57.4,28.28 IC6.61
N$43
  Bottom 0.254: IC6.62 58.03,28.41 56.76,29.68 56.76,30.19 D3.K
N$44
  Bottom 0.254: D3.A 59.05,29.93 59.43,29.55 R9.2
N$45
  Bottom 0.254: D4.A 52.06,30.57 52.13,30.64 R10.2
N$46
  Bottom 0.254: 72.77,14.06 72.77,14.04 IC6.96 | 72.77,14.06 R11.2 | 72.77,14.06
PA0
  Bottom 0.254: 48,14.57 | 48,14.57 IC6.36 | 48,14.57 47.87,14.69 39.36,14.69 37.84,16.22 37.84,34.51 40.63,37.3 JP2.5
  Bottom 0.305: JP2.5 40.63,38.57 41.9,39.84 41.9,45.55 43.81,47.46 43.81,50 44.56,50.75 IC1.51
PA1
  Bottom 0.254: 43.17,39.84 43.17,39.71 43.05,39.71 41.9,38.57 41.9,37.17 38.35,33.62 38.35,16.6 39.62,15.33 47.87,15.33 47.88,15.34 IC6.37
  Bottom 0.305: 45.68,49.96 IC1.50 | 45.68,49.96 45.71,50 | 45.68,49.96 45.08,49.37 45.08,46.83 43.17,44.92 JP2.8 43.17,39.84
PA2
  Bottom 0.254: JP2.7 43.17,36.92 38.86,32.6 38.86,16.98 39.87,15.96 48,15.96 IC6.38
  Bottom 0.305: JP2.7 43.17,38.57 44.45,39.84 44.45,44.29 46.84,46.69 IC1.49
PA3
  Bottom 0.254: JP2.10 45.71,39.84 44.57,38.7 44.57,37.55 39.36,32.35 39.36,17.23 40,16.6 48,16.6 IC6.39
  Bottom 0.305: IC1.48 48.7,46.63 45.71,43.65 JP2.10
PA4
  Bottom 0.254: JP2.9 45.71,37.81 39.87,31.97 39.87,17.74 40.38,17.23 47.87,17.23 48,17.36 | 48,17.36 | 48,17.36 IC6.40
  Bottom 0.305: IC1.47 49.49,46.15 46.98,43.65 46.98,39.84 45.71,38.57 JP2.9
PA5
  Bottom 0.254: JP2.12 48.25,39.97 46.98,38.7 46.98,37.43 45.97,36.41 45.21,36.41 40.38,31.59 40.38,18.25 40.76,17.87 47.87,17.87 48,18 | 48,18 | 48,18 IC6.41
  Bottom 0.305: IC1.46 50.27,45.03 48.25,43.02 JP2.12
PA6
  Bottom 0.254: JP2.11 48.25,37.55 46.35,35.65 45.33,35.65 40.89,31.2 40.89,18.89 41.14,18.63 47.87,18.63 48,18.63 | 48,18.63 | 48,18.63 IC6.42
  Bottom 0.305: IC1.45 51.06,44.55 49.52,43.02 49.52,39.84 48.25,38.57 JP2.11
PA7
  Bottom 0.254: JP2.14 50.79,39.84 49.65,38.7 49.65,37.55 47.11,35.01 45.59,35.01 41.52,30.95 41.52,19.52 41.78,19.27 48,19.27 IC6.43
  Bottom 0.305: IC1.44 51.85,43.43 50.79,42.38 JP2.14
PC0
  Bottom 0.254: JP2.21 60.95,36.54 61.21,36.28 74.54,36.28 86.23,24.6 86.23,10.38 80.26,4.41 67.81,4.41 67.18,5.04 67.18,8.09 67.05,8.22 IC6.5
  Bottom 0.305: IC1.35 58.94,45.67 62.22,42.38 62.22,39.2 JP2.21
PC1
  Bottom 0.254: JP2.22 60.95,39.59 59.68,38.32 59.68,36.79 60.83,35.65 73.78,35.65 85.09,24.35 85.09,10.63 81.02,6.57 73.15,6.57 69.72,10 66.04,10 65.78,9.74 65.78,8.09 65.84,8.15 IC6.7
  Bottom 0.305: IC1.36 58.15,45.19 60.95,42.38 JP2.22
PC2
  Bottom 0.254: JP2.19 58.41,36.79 60.19,35.01 72.89,35.01 83.94,23.96 83.94,10.88 80.77,7.71 72.77,7.71 69.97,10.5 65.53,10.5 65.15,10.12 65.15,8.22 IC6.8
  Bottom 0.305: IC1.37 57.36,44.7 59.68,42.38 59.68,39.2 JP2.19
PC3
  Bottom 0.254: JP2.20 58.41,39.84 57.14,38.57 57.14,37.05 59.81,34.38 72,34.38 82.8,23.58 82.8,11.14 80.51,8.85 72.39,8.85 70.1,11.14 65.4,11.14 64.64,10.38 64.64,8.22 64.55,8.12 | 64.55,8.12 64.51,8.09 | IC6.9 64.55,8.12
  Bottom 0.305: IC1.38 56.57,44.22 58.41,42.38 JP2.20
PC4
  Bottom 0.254: IC6.10 63.88,8.22 63.88,10.5 65.02,11.65 70.35,11.65 72,10 80.26,10 81.66,11.39 81.66,23.2 71.12,33.74 59.56,33.74 55.88,37.43 JP2.17 55.88,38.57 57.14,39.84 57.14,42.51 55.75,43.9 55.75,47.21 55.79,47.24 IC1.39
PC5
  Bottom 0.254: JP2.18 55.88,39.84 54.6,38.57 54.6,37.3 55.49,36.41 56,36.41 59.3,33.11 69.59,33.11 72.89,29.81 72.89,26.25 70.1,23.46 70.1,17.62 66.29,13.81 56.13,13.81 51.56,9.23 51.56,8.22 IC6.29
  Bottom 0.305: IC1.40 55,43.26 55.88,42.38 JP2.18
PC6
  Bottom 0.254: JP2.15 53.34,37.55 55.11,35.78 55.75,35.78 59.05,32.47 68.7,32.47 72.26,28.92 72.26,26.38 69.46,23.58 69.46,17.87 66.04,14.44 56,14.44 50.92,9.36 50.92,8.22 IC6.30
  Bottom 0.305: IC1.41 54.21,42.77 54.6,42.38 54.6,39.84 53.34,38.57 JP2.15
PC7  (via drill 0.61)
  Top 0.254: v42.92,12.79 v42.92,21.04
  Bottom 0.254: JP2.16 53.34,39.84 52.06,38.57 52.06,37.3 50.92,36.16 49.27,36.16 47.49,34.38 46.48,34.38 42.92,30.82 v42.92,21.04 | IC6.33 48,12.79 v42.92,12.79
  Bottom 0.305: IC1.42 53.42,40.56 JP2.16
PE4  (via drill 0.3 pad 0.41, 0.61)
  Top 0.305: 50.16,5.55 v72.39,5.55 | 33.65,3.65 32.38,4.92 32.38,42.38 30.48,44.29 30.48,63.97 31.75,65.24 v52.7,65.24
  Top 0.406: 50.16,5.55 48.25,3.65 33.65,3.65
  Bottom 0.305: JP1.14 52.06,80.48 52.06,69.68 52.64,69.11 IC1.6 52.7,62.9 v52.7,65.24 | IC6.4 67.8,6.33 68.58,5.55 v72.39,5.55
PIN1
  Bottom 0.406: SJ1.3 43.81,74.77 45.71,76.67 JP1.9
PIN2
  Bottom 0.305: IC1.2 49.49,64.64 46.98,67.14 46.98,80.48 JP1.10 45.71,84.29 45.08,84.92 33.78,84.92 33.14,84.29 33.02,53.18 32.38,52.54 IC3.15 29.21,52.54
PIN3  (via drill 1.02)
  Top 0.305: v30.48,70.32 v48.25,70.32
  Bottom 0.305: IC1.3 50.27,65.76 48.25,67.78 v48.25,70.32 JP1.11 | v30.48,70.32 30.48,64.6 27.3,61.43 27.3,56.35 26.03,55.08 IC3.4
PIN4
  Bottom 0.305: IC1.4 51.06,66.88 49.52,68.41 49.52,80.48 JP1.12
PIN5
  Bottom 0.305: IC1.5 51.85,68 50.79,69.05 JP1.13
PIN7
  Bottom 0.305: IC1.7 53.42,79.12
  Bottom 0.406: 53.42,79.12 JP1.15
PIN8
  Bottom 0.305: IC1.8 54.21,71.83 54.6,72.22 54.6,80.48 JP1.16
PIN9
  Bottom 0.305: IC1.9 55,70.71 55.88,71.59 JP1.17
PIN10
  Bottom 0.305: IC1.10 55.79,69.6 57.14,70.95 57.14,80.48 JP1.18
PIN11  (via drill 1.02)
  Top 0.305: v18.41,74.13 v58.41,74.13
  Bottom 0.305: IC1.11 56.57,68.48 58.41,70.32 v58.41,74.13 JP1.19 | SV1.7 v18.41,74.13
PIN12
  Bottom 0.305: IC1.12 57.36,67.36 59.68,69.68 59.68,80.48 JP1.20
PIN13
  Bottom 0.305: IC1.13 58.15,66.24 60.95,69.05 JP1.21
PIN14
  Bottom 0.305: JP1.22 62.22,80.48 62.22,68.41 58.94,65.13 IC1.14
PIN15
  Bottom 0.305: IC1.15 59.72,64.01 63.49,67.78 JP1.23
PIN16
  Bottom 0.305: IC1.16 64.77,67.09 64.77,80.48 JP1.24
PIN17
  Bottom 0.305: IC1.17 62.22,60.99 62.22,62.06 66.04,65.88 JP1.25
PIN25
  Bottom 0.305: JP2.31 74.29,37.94 75.56,39.2 75.56,40.48 76.2,41.11 IC4.6 80.01,41.11 80.64,41.74 80.64,44.29 79.37,45.55 78.1,45.55 76.83,46.83 76.83,49.37 75.56,50.63 R6.1 75.43,50.13 70.87,54.69 IC1.25
PIN26
  Bottom 0.305: IC1.26 69.76,53.9 73.66,50 73.66,49.37 74.93,48.09 | 75.56,48.09 R7.1 74.93,48.09 | JP2.32 73.66,42.38 74.93,43.65 | 74.93,43.65 73.66,44.92 73.66,46.83 74.93,48.09 | 74.93,43.65 IC4.5
PIN27
  Bottom 0.305: IC1.27 68.64,53.11 72.39,49.37 72.39,39.2 JP2.29
PIN28
  Bottom 0.305: IC1.28 67.52,52.32 71.12,48.73 JP2.30
PIN29
  Bottom 0.305: JP2.27 69.84,39.2 69.84,48.09 66.4,51.54 IC1.29
PIN30
  Bottom 0.305: IC1.30 65.29,50.75 68.58,47.46 JP2.28
PIN31
  Bottom 0.305: JP2.25 67.31,39.2 67.31,46.83 64.17,49.96 IC1.31
PIN32
  Bottom 0.305: JP2.26 66.04,46.19 63.05,49.18 IC1.32
PIN33
  Bottom 0.305: IC1.33 60.51,47.27 64.77,43.02 64.77,39.2 JP2.23
PIN34
  Bottom 0.305: IC1.34 59.72,46.15 63.49,42.38 JP2.24
PIN43
  Bottom 0.305: IC1.43 52.64,42.95 52.06,42.38 52.06,39.84 50.79,38.57 JP2.13
PIN54
  Bottom 0.305: IC1.54 39.94,53.11 38.09,51.27 JP2.4
PIN55
  Bottom 0.305: JP2.1 36.82,39.2 36.82,52.54 38.18,53.9 IC1.55
PIN56
  Bottom 0.305: IC1.56 37.07,54.69 35.55,53.18 JP2.2
PIN57
  Bottom 0.305: IC1.57 37.07,55.47 35.55,56.98 JP1.1
PIN58
  Bottom 0.254: 36.82,80.48 36.82,76.16 36.44,75.78 36.44,58 38.18,56.26 38.22,56.22
  Bottom 0.305: 36.82,80.48 JP1.2 | 38.18,56.26 IC1.58
PIN59
  Bottom 0.254: JP1.3 38.09,75.91 37.33,75.15 37.33,58.38 38.65,57.04 39.8,57.04 39.94,57.05
  Bottom 0.305: 39.94,57.05 IC1.59
PIN60
  Bottom 0.254: 39.36,80.48 39.49,80.35 39.49,76.03 38.09,74.64 38.09,58.64 38.88,57.85 41.04,57.85 41.05,57.84
  Bottom 0.305: 39.36,80.48 JP1.4 | 41.05,57.84 IC1.60
PIN61
  Bottom 0.254: JP1.5 40.63,76.03 38.98,74.38 38.98,59.27 39.62,58.64 42.16,58.64 42.17,58.62
  Bottom 0.305: 42.17,58.62 IC1.61
PIN62
  Bottom 0.254: 41.9,80.48 41.9,76.16 39.75,74 39.75,59.91 40.25,59.4 43.3,59.4 43.29,59.41
  Bottom 0.305: 41.9,80.48 JP1.6 | 43.29,59.41 IC1.62
RES
  Bottom 0.305: JP1.28 69.84,80.48 69.84,62.06 66.4,58.62 IC1.20 | R4.1 30.98,78.07 31.75,77.3 31.75,60.8 31.11,60.16 IC3.9 29.74,58.99 29.84,58.89 IC3.10 29.74,57.72 29.84,57.62 IC3.11
  Bottom 0.406: 27.94,81.75 32.38,86.19 66.67,86.19 68.58,84.29 JP1.28 | R1.1 25.39,77.94 25.53,78.07 | 3.81,84.29 3.83,83.63 S1.2
  Bottom 0.61: R4.1 27.94,80.48 | 27.94,80.48 C1.+ | 27.94,80.48 27.94,81.75 26.05,83.63 9.49,83.63 9.49,83.68 8.25,84.92 4.44,84.92 3.81,84.29
  Bottom 1.016: R4.1 25.53,78.07
VCC  (via drill 0.61, 0.61 pad 1.02, 0.81, 1.02)
  Top 0.254: v44.95,11.77 v44.95,21.81 | v66.29,29.05 v74.16,29.05
  Top 0.305: v71.12,67.78 v25.39,67.78 | v33.02,46.19 v40.63,46.19 | 46.12,11.73 v46.12,6.06
  Top 0.406: v46.16,11.77 46.12,11.73
  Bottom 0.254: IC6.89 72.64,18.63 C20.1 | 54.73,27.01 IC6.57 | IC6.6 66.5,6.52 66.04,6.06 60.45,6.06 59.94,6.57 | 59.94,6.57 59.94,8.22 60.07,8.22 | IC6.15 60.58,8.22 60.57,8.22 60.07,8.22 | 59.31,8.22 IC6.17 | 59.31,8.22 IC6.16 60.06,8.22 60.07,8.22 | 59.31,8.22 59.3,8.22 | 48,11.77 IC6.31 | 48,11.77 45.33,11.77 v44.95,11.77 | v46.12,6.06 59.56,6.06 59.94,6.44 59.94,6.57 | v44.95,21.81 45.24,21.84 IC6.47 48,21.93 50.92,21.93 54.73,25.74 54.73,27.01 | C20.1 75.43,27.78 v74.16,29.05 | C20.1 | v66.29,29.05 65.65,29.05 65.02,29.55 63.24,29.55 | IC6.32 48,12.03 48,11.77 | 32.51,34.76 32.38,34.76 | R10.1 54.03,32.54 53.34,31.84 53.34,29.43 53.84,28.92 54.22,28.92 54.73,28.41 54.73,27.14 54.86,27.01 54.73,27.01 | 62.73,29.55 R9.1 63.24,29.55 | 63.24,29.55 IC6.70 63.24,24.48 62.73,24.09 60.57,24.09 60.07,24.6 60.07,27.01 60.06,27.01 IC6.65 59.99,28.23 59.56,28.66 58.8,28.66 57.78,29.68 57.78,30.82 55.24,33.36 R10.1 | R10.1 53.97,33.36
  Bottom 0.305: v71.12,67.78 71.12,61.43 67.52,57.84 IC1.21 | 19.68,67.78 v25.39,67.78 25.39,70.32 27.94,72.86 R4.2 | 72.39,72.86 C9.1 | 72.26,75.27 72.39,75.4 R5.2 72.26,76.16 | 41.77,47.97 42.54,48.73 42.54,50.63 43.44,51.54 IC1.52 | IC1.64 46.84,62.84 45.08,64.6 43.81,64.6 C11.1 | 59.9,57.84 59.9,58.04 | C6.2 29.84,31.59 29.74,31.69 IC2.16 32.38,34.76 33.02,35.4 v33.02,46.19 33.02,50.63 32.38,51.27 IC3.16 | 19.68,67.78 C8.1 | SV1.2 9.52,66.51 10.79,67.78 19.68,67.78 | v40.63,46.19 40.63,47.46 41.27,48.09 | C20.1 | C20.1 | C20.1 | 53.97,33.36 53.98,33.37 53.98,33.36 R10.1
  Bottom 0.406: IC1.52 58.05,51.54 59.05,52.54 59.05,56.98 59.9,57.84 IC1.21 | 59.9,58.04 59.05,58.89 59.05,60.16 58.22,60.99 IC1.64 | C10.1 41.27,48.09 41.4,47.97 41.77,47.97 | 43.81,69.68 SJ1.1 C11.1 | 78.1,68.41 R8.2 | 32.51,34.76 36.44,30.82 36.44,13.55 38.22,11.77 45.33,11.77 v44.93,11.77 44.93,11.77 | 44.93,11.77 v46.16,11.77 | 44.93,11.77 44.87,11.71
  Bottom 0.61: v71.12,67.78 72.39,69.05 72.39,70.32 | 72.39,70.32 72.39,72.86 | C9.1 72.26,75.27 | 72.26,76.16 71.12,77.3 JP1.29 | 72.39,70.32 75.56,70.32 77.47,68.41 78.1,68.41 79.37,68.41 80.01,69.05 IC5.OUT

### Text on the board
Bottom: PCB 1.4 | Ulrich Radig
